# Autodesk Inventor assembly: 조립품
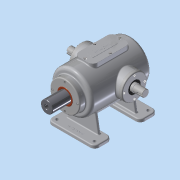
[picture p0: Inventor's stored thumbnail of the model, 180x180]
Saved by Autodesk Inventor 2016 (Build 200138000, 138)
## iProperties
Created: 2018-11
Part Number: 조립품
Material: 일반
Document SubType Name: Assembly
Designer: user
Mass: 8191.31 g
Surface Area: 4241.88 cm^2
Volume: 1855.5 cm^3
Density: 4.4146 g/cm^3
Author: user
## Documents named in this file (15)
- C:\Users\user\Desktop\381121V1011\조립품.iam
- C:\Users\user\Desktop\381121V1011\가변스프링.ipt
- C:\Users\user\Desktop\381121V1011\베어링 6205.ipt
- 베어링 6205.ipt
- C:\Users\user\Desktop\381121V1011\본체.ipt
- C:\Users\user\Desktop\381121V1011\볼트 M4x0.7.ipt
- C:\Users\user\Desktop\381121V1011\부시.ipt
- C:\Users\user\Desktop\381121V1011\상부커버.ipt
- C:\Users\user\Desktop\381121V1011\슬라이드 커버.ipt
- C:\Users\user\Desktop\381121V1011\슬라이드.ipt
- C:\Users\user\Desktop\381121V1011\오일실.ipt
- 오일실.ipt
- C:\Users\user\Desktop\381121V1011\육각머리볼트 M4.ipt
- C:\Users\user\Desktop\381121V1011\축 커버.ipt
- C:\Users\user\Desktop\381121V1011\편심축.ipt
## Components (13 placed, 2 different names)
1. 가변스프링:1
2. M4x0.7:2
3. M4x0.7:3
4. M4x0.7:4
5. M4x0.7:5
6. M4x0.7:1
7. M4x0.7:6
8. M4x0.7:7
9. M4x0.7:8
10. M4x0.7:9
11. M4x0.7:10
12. M4x0.7:11
13. M4x0.7:12
